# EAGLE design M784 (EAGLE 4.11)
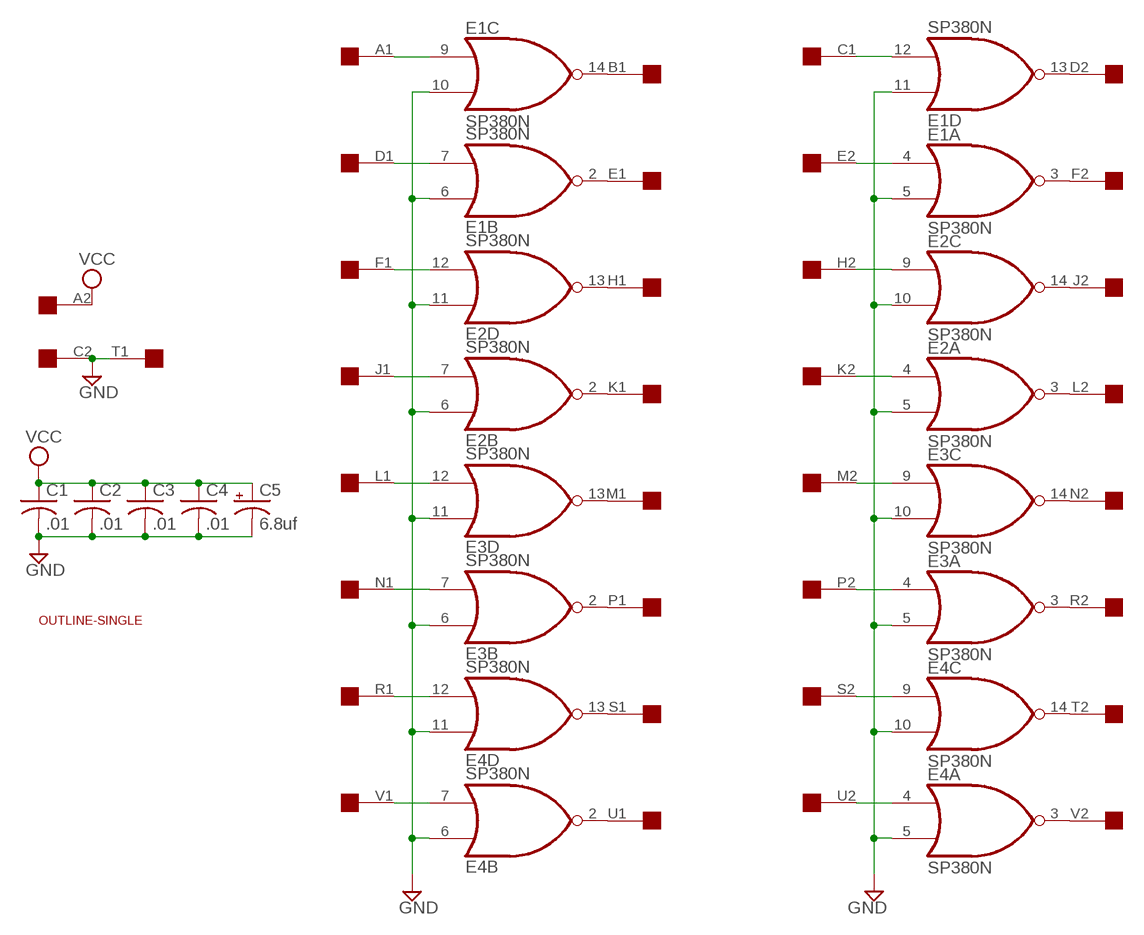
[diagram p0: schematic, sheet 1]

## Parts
C1  .01  C-US050-025X075  [C050-025X075]
C2  .01  C-US050-025X075  [C050-025X075]
C3  .01  C-US050-025X075  [C050-025X075]
C4  .01  C-US050-025X075  [C050-025X075]
C5  6.8uf  CPOL-USE15-5AXIAL  [E15-5]
E1  SP380N  [DIL14]
E2  SP380N  [DIL14]
E3  SP380N  [DIL14]
E4  SP380N  [DIL14]
U$1  SINGLE  [EDGE-CON2]
U$2  OUTLINE-SINGLE  [SINGLE]

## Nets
GND: C1.2 C2.2 C3.2 C4.2 C5.- E1.5(A:I1) E1.6(B:I0) E1.10(C:I1) E1.11(D:I0) E2.5(A:I1) E2.6(B:I0) E2.10(C:I1) E2.11(D:I0) E3.5(A:I1) E3.6(B:I0) E3.10(C:I1) E3.11(D:I0) E4.5(A:I1) E4.6(B:I0) E4.10(C:I1) E4.11(D:I0) U$1.C2 U$1.T1
N$1: E3.13(D:O) U$1.M1
N$2: E3.12(D:I1) U$1.L1
N$3: E1.4(A:I0) U$1.E2
N$4: E1.3(A:O) U$1.F2
N$5: E3.7(B:I1) U$1.N1
N$6: E2.13(D:O) U$1.H1
N$7: E2.4(A:I0) U$1.K2
N$8: E1.2(B:O) U$1.E1
N$9: E2.7(B:I1) U$1.J1
N$10: E4.2(B:O) U$1.U1
N$11: E2.2(B:O) U$1.K1
N$12: E4.7(B:I1) U$1.V1
N$13: E3.2(B:O) U$1.P1
N$14: E1.13(D:O) U$1.D2
N$15: E4.12(D:I1) U$1.R1
N$16: E4.13(D:O) U$1.S1
N$17: E1.12(D:I1) U$1.C1
N$18: E2.3(A:O) U$1.L2
N$19: E2.14(C:O) U$1.J2
N$20: E2.9(C:I0) U$1.H2
N$21: E3.14(C:O) U$1.N2
N$22: E3.3(A:O) U$1.R2
N$23: E4.14(C:O) U$1.T2
N$24: E4.3(A:O) U$1.V2
N$25: E1.14(C:O) U$1.B1
N$26: E3.9(C:I0) U$1.M2
N$27: E3.4(A:I0) U$1.P2
N$28: E2.12(D:I1) U$1.F1
N$29: E4.9(C:I0) U$1.S2
N$30: E1.7(B:I1) U$1.D1
N$31: E4.4(A:I0) U$1.U2
N$32: E1.9(C:I0) U$1.A1
VCC: C1.1 C2.1 C3.1 C4.1 C5.+ U$1.A2
Unconnected: U$1.B2

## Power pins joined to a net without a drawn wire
GND: E1.1(P:GND) E2.1(P:GND) E3.1(P:GND) E4.1(P:GND)
VCC: E1.8(P:VCC) E2.8(P:VCC) E3.8(P:VCC) E4.8(P:VCC)

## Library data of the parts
C1-C4 = rcl:C-US: CAPACITOR, American symbol
C5 = rcl:CPOL-US: POLARIZED CAPACITOR, American symbol
E1-E4 = dec-con:SP380: Quad NOR gate (use 8640)
U$1 = dec-con:SINGLE: Single-Height DEC board
U$2 = dec-con:OUTLINE-*: Board outlines for DEC boards.

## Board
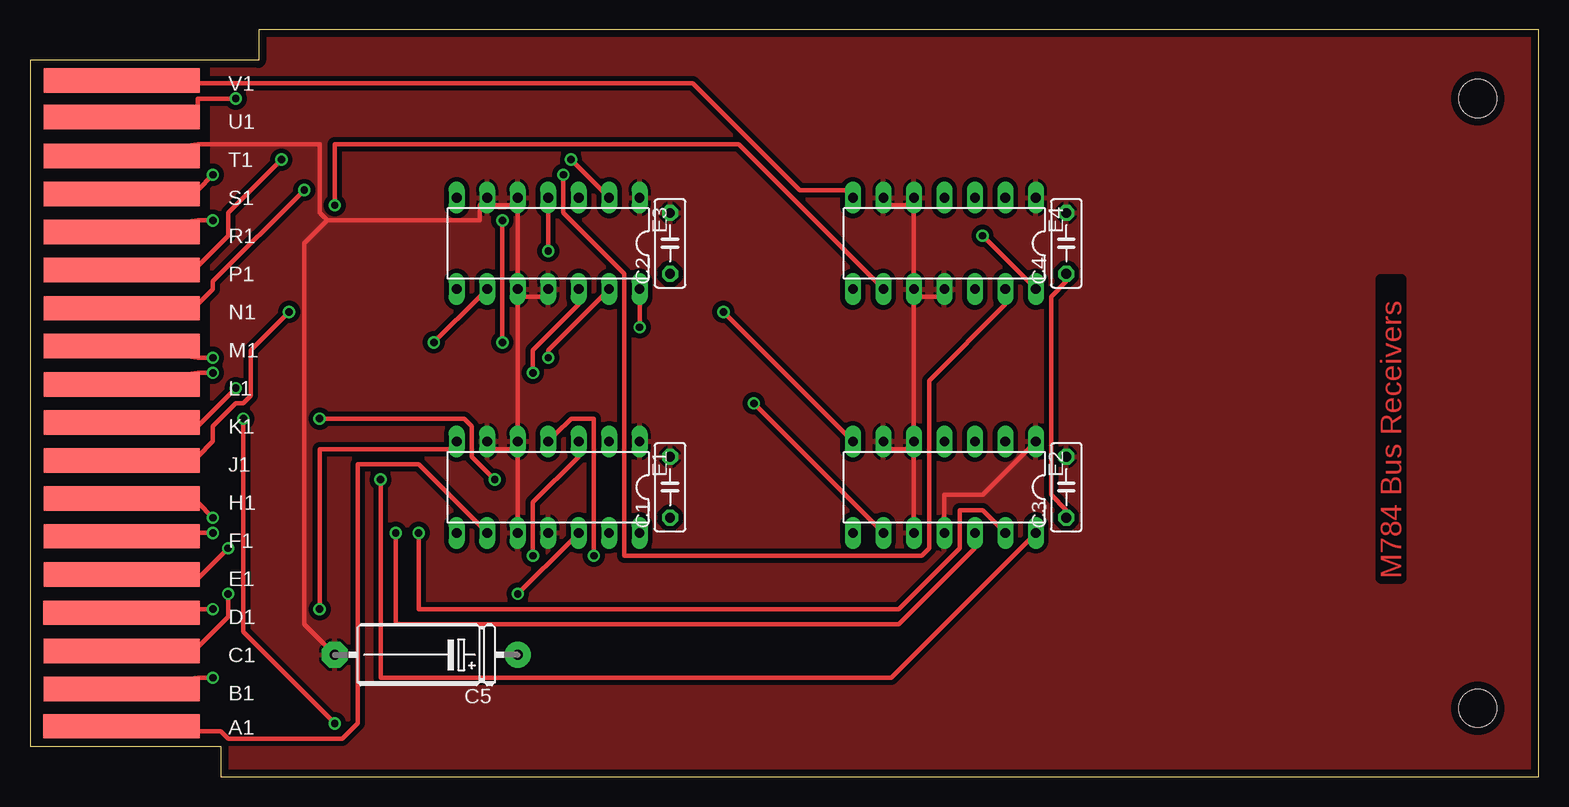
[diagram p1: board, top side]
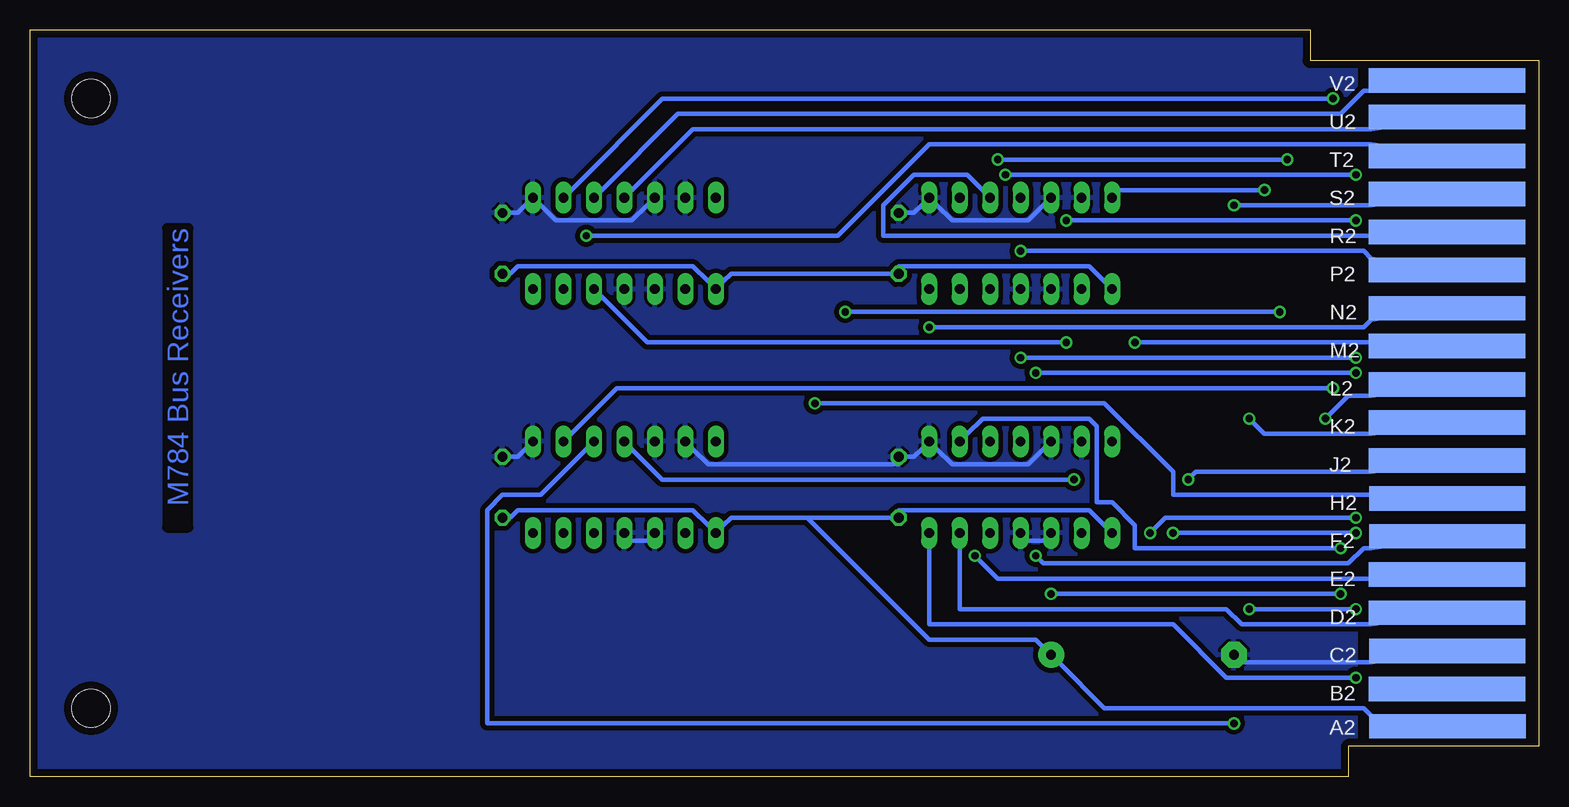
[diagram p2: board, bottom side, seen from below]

Size 125.73 x 62.23 mm. Coordinates in mm from the lower left corner, seen from the top.
Copper layers (1*16): Top 0.035mm / dielectric 1.5mm / Bottom 0.035mm
Design rules "15mils": minimum track width 15mil, minimum drill 24mil, track to track 15mil, track to pad 10mil, pad to pad 10mil, via to via 10mil, smd to smd 10mil, copper to edge 25mil, drill to drill 10mil, minimum pad ring 10mil, minimum via ring 8mil, stop-mask expansion 0mil, vias tented up to drill 0mil, thermal gap 10mil

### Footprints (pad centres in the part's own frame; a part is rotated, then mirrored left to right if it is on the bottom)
C050-025X075 = drill 0.813 octagon: 1 -2.54,0; 2 2.54,0
E15-5 = drill 0.813 pad 2.159 round: + -7.62,0 | drill 0.813 pad 2.159 octagon: - 7.62,0
DIL14 = drill 0.813 long: 1 -7.62,-3.81; 2 -5.08,-3.81; 3 -2.54,-3.81; 4 0,-3.81; 5 2.54,-3.81; 6 5.08,-3.81; 7 7.62,-3.81; 8 7.62,3.81; 9 5.08,3.81; 10 2.54,3.81; 11 0,3.81; 12 -2.54,3.81; 13 -5.08,3.81; 14 -7.62,3.81
EDGE-CON2 = smd 13.017 x 2.032: A1 7.633,4.207; B1 7.639,7.327; C1 7.636,10.489; D1 7.633,13.665; E1 7.642,16.84; F1 7.642,20.041; H1 7.642,23.19; J1 7.642,26.34; K1 7.642,29.515; L1 7.642,32.69; M1 7.642,35.89; N1 7.642,39.04; P1 7.642,42.24; R1 7.642,45.39; S1 7.642,48.565; T1 7.642,51.74; U1 7.642,54.966; V1 7.642,58.026 | smd 13.017 x 2.032 bottom: A2 7.614,4.207; B2 7.642,7.328; C2 7.617,10.49; D2 7.642,13.665; E2 7.642,16.84; F2 7.617,20.041; H2 7.617,23.19; J2 7.642,26.34; K2 7.642,29.515; L2 7.642,32.69; M2 7.642,35.89; N2 7.642,39.04; P2 7.642,42.24; R2 7.642,45.39; S2 7.642,48.565; T2 7.642,51.74; U2 7.642,54.966; V2 7.642,58.026
SINGLE = hole 3.175: 120.65,56.515; 120.65,5.715

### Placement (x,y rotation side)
C1  53.34,24.13 90 top
C2  53.34,44.45 90 top
C3  86.36,24.13 90 top
C4  86.36,44.45 90 top
C5  33.02,10.16 180 top
E1  43.18,24.13 180 top
E2  76.2,24.13 180 top
E3  43.18,44.45 180 top
E4  76.2,44.45 180 top
U$1  0,0 0 top
U$2  0,0 0 top

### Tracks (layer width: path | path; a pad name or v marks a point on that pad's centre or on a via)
GND
  Top 0.381: E2.6 71.76,27.3 73.03,27.3 E2.5 | E2.5 73.66,26.67 73.66,21.59 E2.10 | E2.1 83.19,27.3 79.38,23.5 76.2,23.5 76.2,21.59 E2.11 | E4.6 71.76,47.62 73.03,47.62 E4.5 73.66,46.99 73.66,41.91 E4.10 | E4.10 74.3,40.01 75.57,40.01 E4.11 | E2.5 73.66,29.21 73.66,39.37 E4.10 | E1.6 38.74,27.3 40.01,27.3 E1.5 | E1.5 40.64,26.67 40.64,21.59 E1.10 | E3.10 41.28,40.01 42.55,40.01 E3.11 | E3.10 40.64,41.91 40.64,46.99 E3.5 40.01,47.62 38.74,47.62 E3.6 37.47,47.62 37.47,46.35 24.77,46.35 | E1.5 40.64,29.21 40.64,39.37 E3.10 | 24.77,46.35 24.13,46.99 24.13,52.7 13.97,52.7 U$1.T1 | 24.77,46.35 22.86,44.45 22.86,12.7 24.77,10.79 C5.-
  Bottom 0.381: E2.1 84.46,27.3 85.09,26.67 85.73,26.67 C3.2 | E2.10 74.3,19.68 75.57,19.68 E2.11 | C4.2 85.73,46.99 85.09,46.99 84.46,47.62 E4.1 83.19,47.62 81.92,46.35 75.57,46.35 74.3,47.62 E4.5 | C5.- 24.77,9.53 13.97,9.53 U$1.C2 | E1.10 41.28,19.68 42.55,19.68 E1.11 | E1.5 41.28,27.3 42.55,26.04 48.9,26.04 50.17,27.3 E1.1 51.44,27.3 52.07,26.67 52.71,26.67 C1.2 53.34,26.04 69.22,26.04 70.49,27.3 E2.6 | C2.2 52.71,46.99 52.07,46.99 51.44,47.62 E3.1 50.17,47.62 48.9,46.35 42.55,46.35 41.28,47.62 E3.5
  pour Top (isolate 0.406): 15.24,62.23 125.73,62.23 125.73,0 15.24,0
  pour Bottom (isolate 0.406): 15.24,62.23 125.73,62.23 125.73,0 15.24,0
N$1  (via drill 0.61)
  Top 0.381: v43.18,34.92 43.18,35.56 47.63,40.01 E3.13 | v15.24,34.92 13.97,34.92 U$1.M1
  Bottom 0.381: v15.24,34.92 v43.18,34.92
N$2  (via drill 0.61)
  Top 0.381: v41.91,33.66 41.91,35.56 45.72,39.37 E3.12 | v15.24,33.66 13.97,33.66 U$1.L1
  Bottom 0.381: v15.24,33.66 v41.91,33.66
N$3  (via drill 0.61)
  Top 0.381: v46.99,18.41 46.99,29.84 45.09,29.84 43.82,28.57 E1.4
  Bottom 0.381: v46.99,18.41 45.09,16.51 13.97,16.51 U$1.E2
N$4  (via drill 0.61)
  Top 0.381: v41.91,18.41 41.91,22.86 45.72,26.67 E1.3
  Bottom 0.381: v41.91,18.41 41.28,17.78 15.88,17.78 14.61,19.05 13.97,19.05 U$1.F2
N$5  (via drill 0.61)
  Top 0.381: v22.86,48.9 15.24,41.27 15.24,40.64 13.97,39.37 U$1.N1
  Bottom 0.381: v22.86,48.9 34.93,48.9 E3.7
N$6  (via drill 0.61)
  Top 0.381: v32.39,20.32 32.39,13.97 72.39,13.97 77.47,19.05 77.47,22.23 79.38,22.23 80.65,20.95 E2.13 | v15.24,21.59 13.97,22.86 U$1.H1
  Bottom 0.381: v32.39,20.32 31.12,21.59 v15.24,21.59
N$7  (via drill 0.61)
  Top 0.381: v38.74,24.77 36.83,26.67 36.83,29.21 36.2,29.84 v24.13,29.84
  Bottom 0.381: v38.74,24.77 73.03,24.77 75.57,27.3 E2.4 | v24.13,29.84 22.86,28.57 13.97,28.57 U$1.K2
N$8  (via drill 0.61)
  Top 0.381: v16.51,19.05 13.97,16.51 U$1.E1
  Bottom 0.381: v16.51,19.05 33.66,19.05 33.66,20.95 35.56,22.86 36.83,22.86 36.83,29.21 37.47,29.84 46.36,29.84 47.63,28.57 E1.2
N$9  (via drill 0.61)
  Top 0.381: v57.79,38.73 67.95,28.57 E2.7 | v21.59,38.73 18.42,35.56 18.42,31.75 17.78,31.11 17.15,31.11 15.24,29.21 15.24,27.94 13.97,26.67 U$1.J1
  Bottom 0.381: v21.59,38.73 v57.79,38.73
N$10  (via drill 0.61)
  Top 0.381: v17.15,56.52 13.97,56.52 13.97,55.88 U$1.U1
  Bottom 0.381: v17.15,56.52 73.03,56.52 80.65,48.9 E4.2
N$11  (via drill 0.61)
  Top 0.381: v17.15,32.38 13.97,29.21 U$1.K1
  Bottom 0.381: v17.15,32.38 76.84,32.38 80.65,28.57 E2.2
N$12
  Top 0.381: E4.7 67.95,48.9 64.14,48.9 55.25,57.78 13.97,57.78 U$1.V1
N$13  (via drill 0.61)
  Top 0.381: v45.09,51.44 47.63,48.9 E3.2 | v20.96,51.44 16.51,46.99 16.51,45.09 13.97,42.55 U$1.P1
  Bottom 0.381: v20.96,51.44 v45.09,51.44
N$14
  Bottom 0.381: E1.13 48.26,19.05 48.26,13.97 26.04,13.97 24.77,12.7 13.97,12.7 U$1.D2
N$15  (via drill 0.61)
  Top 0.381: v39.37,46.35 v39.37,36.2 | v15.24,46.35 13.97,46.35 U$1.R1
  Bottom 0.381: v39.37,36.2 74.3,36.2 78.11,40.01 E4.12 | v15.24,46.35 v39.37,46.35
N$16  (via drill 0.61)
  Top 0.381: v44.45,50.16 44.45,46.99 49.53,41.91 49.53,18.41 74.3,18.41 74.93,19.05 74.93,33.02 81.28,39.37 E4.13 | v15.24,50.16 13.97,48.9 U$1.S1
  Bottom 0.381: v15.24,50.16 v44.45,50.16
N$17  (via drill 0.61)
  Top 0.381: v40.64,15.24 45.09,19.68 E1.12 | v16.51,15.24 16.51,13.34 13.97,10.79 U$1.C1
  Bottom 0.381: v16.51,15.24 v40.64,15.24
N$18  (via drill 0.61)
  Top 0.381: v25.4,4.45 17.78,12.06 v17.78,29.84
  Bottom 0.381: v25.4,4.45 87.63,4.45 87.63,22.23 86.36,23.5 83.19,23.5 79.38,27.3 E2.3 | v17.78,29.84 15.88,31.75 13.97,31.75 U$1.L2
N$19  (via drill 0.61)
  Top 0.381: v29.21,24.77 29.21,8.26 71.76,8.26 83.19,19.68 E2.14
  Bottom 0.381: v29.21,24.77 28.58,25.4 13.97,25.4 U$1.J2
N$20  (via drill 0.61)
  Top 0.381: v60.33,31.11 70.49,20.95 E2.9
  Bottom 0.381: v60.33,31.11 36.2,31.11 30.48,25.4 30.48,23.5 13.97,23.5 U$1.H2
N$21  (via drill 0.61)
  Top 0.381: v50.8,37.47 50.8,39.37 E3.14
  Bottom 0.381: v50.8,37.47 14.61,37.47 13.97,38.1 U$1.N2
N$22
  Bottom 0.381: E3.3 46.36,48.9 47.63,50.16 52.07,50.16 54.61,47.62 54.61,45.09 13.97,45.09 U$1.R2
N$23  (via drill 0.61)
  Top 0.381: v79.38,45.09 83.19,41.27 E4.14
  Bottom 0.381: v79.38,45.09 58.42,45.09 50.8,52.7 13.97,52.7 U$1.T2
N$24
  Bottom 0.381: E4.3 78.11,48.9 71.76,55.24 16.51,55.24 14.61,57.15 13.97,57.15 U$1.V2
N$25  (via drill 0.61)
  Top 0.381: v15.24,8.26 13.97,8.26 U$1.B1
  Bottom 0.381: v15.24,8.26 26.04,8.26 30.48,12.7 50.8,12.7 50.8,19.05 E1.14
N$26  (via drill 0.61)
  Top 0.381: v33.66,36.2 37.47,40.01 E3.9
  Bottom 0.381: v33.66,36.2 13.97,36.2 U$1.M2
N$27  (via drill 0.61)
  Top 0.381: v43.18,43.81 43.18,46.99 E3.4
  Bottom 0.381: v43.18,43.81 14.61,43.81 13.97,43.18 U$1.P2
N$28  (via drill 0.61)
  Top 0.381: v30.48,20.32 30.48,12.7 72.39,12.7 78.74,19.05 E2.12 | v15.24,20.32 13.97,20.32 U$1.F1
  Bottom 0.381: v15.24,20.32 v30.48,20.32
N$29  (via drill 0.61)
  Top 0.381: v25.4,47.62 25.4,52.7 59.06,52.7 70.49,41.27 E4.9
  Bottom 0.381: v25.4,47.62 13.97,47.62 U$1.S2
N$30  (via drill 0.61)
  Top 0.381: v24.13,13.97 24.13,27.3 34.93,27.3 E1.7 | v15.24,13.97 13.97,13.97 U$1.D1
  Bottom 0.381: v15.24,13.97 v24.13,13.97
N$31
  Bottom 0.381: E4.4 75.57,48.9 70.49,53.98 13.97,53.98 U$1.U2
N$32
  Top 0.381: E1.9 37.47,20.95 32.39,26.04 27.31,26.04 27.31,4.45 26.04,3.17 16.51,3.17 15.88,3.81 13.97,3.81 U$1.A1
VCC
  Top 0.381: C4.1 86.36,41.27 85.09,40.01 85.09,23.5 86.36,22.23 C3.1
  Bottom 0.381: E3.8 36.2,41.27 37.47,42.55 53.34,42.55 C2.1 53.98,41.91 67.31,41.91 67.95,41.27 E4.8 69.22,41.27 70.49,42.55 85.09,42.55 85.73,41.91 C4.1 | E1.8 36.2,20.95 37.47,22.23 53.34,22.23 C1.1 53.98,21.59 60.96,21.59 | 60.96,21.59 67.31,21.59 67.95,20.95 E2.8 69.22,20.95 70.49,22.23 85.09,22.23 85.73,21.59 C3.1 | 60.96,21.59 50.8,11.43 41.91,11.43 41.28,10.79 C5.+ 40.01,9.53 36.2,5.71 14.61,5.71 13.97,5.08 U$1.A2

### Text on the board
Top: M784 Bus Receivers
Bottom: M784 Bus Receivers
